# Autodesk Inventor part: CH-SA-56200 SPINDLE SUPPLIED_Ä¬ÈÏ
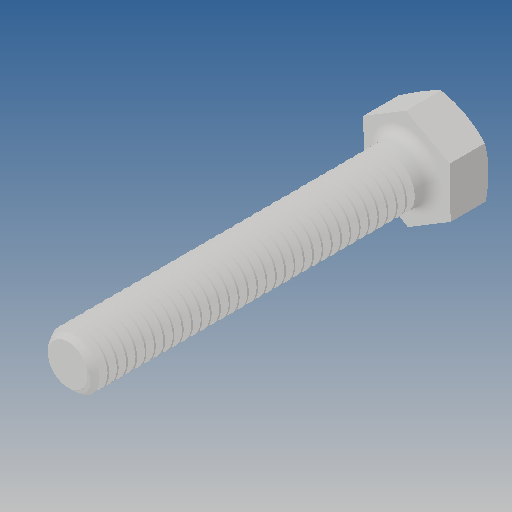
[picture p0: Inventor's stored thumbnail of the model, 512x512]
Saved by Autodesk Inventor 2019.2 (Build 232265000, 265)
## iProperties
Created: 2010-06
Part Number: CH-SA-56200 SPINDLE SUPPLIED_Ä¬ÈÏ
Material: Ogólny
Document SubType Name: Modeling
Designer: CADENGINEERING4
Density: 1 g/cm^3
Appearance: Domyślna
Author: CADENGINEERING4
Revision Number: ÈÎºÎ
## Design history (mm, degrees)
feature "NONE"
node "Bryła1"
